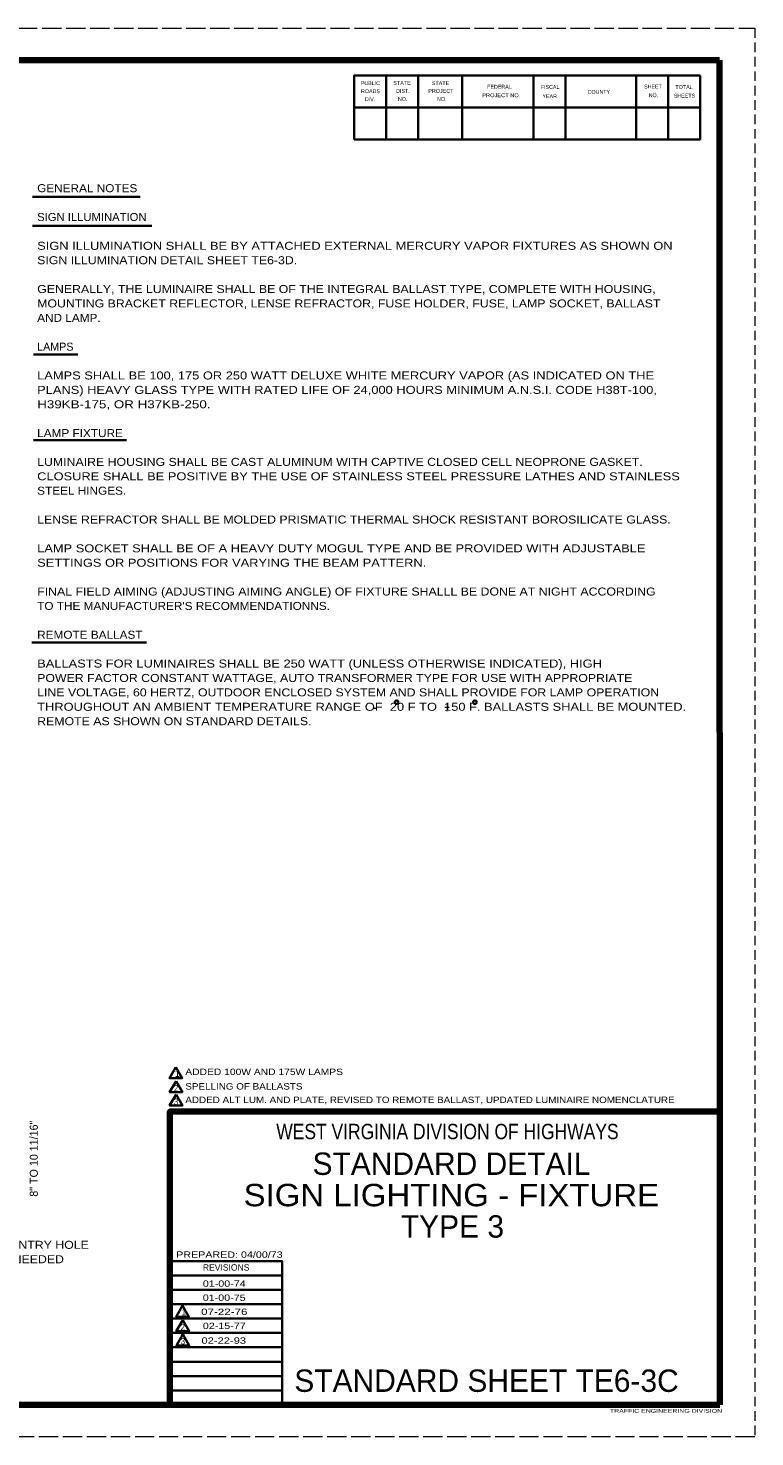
# Model space of a CAD drawing. Extents: x -67 to 613, y -55 to 385.
# Drawn here: x 386.2 to 613.1, y -55.5 to 384.6 of the extents above; entities that cross this region are included whole.
import ezdxf
from ezdxf.enums import TextEntityAlignment as Align

# ---------------------------------------------------------------- set-up
doc = ezdxf.new("R2010")
doc.units = 0
doc.linetypes.add('LONG_DASHED', pattern=[7.5, 6, -1.5])
doc.linetypes.add('MEDIUM_DASHED', pattern=[4.5, 3, -1.5])
doc.layers.add('1', color=7, linetype='Continuous', lineweight=13)
doc.layers.add('61', color=7, linetype='Continuous', lineweight=35)

msp = doc.modelspace()

# ---------------------------------------------------------------- linework, layer by layer
at = {"layer": '1', "linetype": 'MEDIUM_DASHED'}
msp.add_line((613.061, 384.56), (613.041, -55.46), dxfattribs=at)
at = {"layer": '1', "lineweight": 35}
for p, q in [((387.586, 331.879), (421.121, 331.879)), ((387.586, 322.863), (424.831, 322.863)), ((387.868, 282.575), (401.68, 282.575)), ((387.868, 255.811), (416.926, 255.811)), ((387.305, 192.703), (423.13, 192.703)), ((465.441, -5.04), (430.461, -5.04)), ((465.441, -9.54), (430.461, -9.54)), ((465.441, -14.04), (430.461, -14.04)), ((465.441, -18.56), (430.461, -18.56)), ((465.441, -23.04), (430.461, -23.04)), ((465.441, -27.52), (430.461, -27.52)), ((465.441, -32.02), (430.461, -32.02)), ((465.441, -36.52), (430.461, -36.52)), ((465.441, -41.04), (430.461, -41.04))]:
    msp.add_line(p, q, dxfattribs=at)
for points in [[(432.302, 60.038), (430.302, 56.574), (434.302, 56.574)], [(432.358, 55.671), (430.358, 52.207), (434.358, 52.207)], [(432.358, 51.453), (430.358, 47.989), (434.358, 47.989)], [(434.394, -14.481), (432.394, -17.945), (436.394, -17.945)], [(434.432, -19.059), (432.432, -22.523), (436.432, -22.523)], [(434.469, -23.455), (432.469, -26.919), (436.469, -26.919)]]:
    msp.add_lwpolyline(points, close=True, dxfattribs=at)
at = {"layer": '1', "lineweight": 158}
msp.add_lwpolyline([(430.441, -45.48), (430.441, 46.1), (602.101, 46.1)], dxfattribs=at)
at = {"layer": '1', "lineweight": 35}
msp.add_lwpolyline([(465.441, -45.52), (465.441, -0.56), (430.461, -0.56)], dxfattribs=at)
for centre in [(501.246, 174.005), (525.66, 174.005)]:
    msp.add_circle(centre, 0.568, dxfattribs=at)
at = {"layer": '61', "linetype": 'LONG_DASHED', "lineweight": 13}
for p, q in [((-66.959, 384.56), (613.061, 384.56)), ((613.041, -55.46), (-67.019, -55.48))]:
    msp.add_line(p, q, dxfattribs=at)
at = {"layer": '61', "lineweight": 158}
for p, q in [((602.081, 374.56), (602.101, -45.48)), ((602.101, -45.48), (-36.959, -45.46))]:
    msp.add_line(p, q, dxfattribs=at)
at = {"layer": '61'}
for p, q in [((498.001, 369.8), (498.001, 349.8)), ((508.001, 369.8), (508.001, 349.8)), ((521.681, 369.8), (521.681, 349.8)), ((544.001, 369.8), (544.001, 349.8)), ((554.001, 369.8), (554.001, 349.8)), ((575.981, 369.82), (575.981, 349.82)), ((585.981, 369.82), (585.981, 349.82)), ((596.001, 359.78), (487.981, 359.8))]:
    msp.add_line(p, q, dxfattribs=at)
at = {"layer": '61', "lineweight": 158}
msp.add_lwpolyline([(602.081, 374.56), (-36.959, 374.56), (-36.959, -45.46)], dxfattribs=at)
at = {"layer": '61'}
for points in [[(595.981, 369.82), (488.001, 369.8), (488.001, 349.8)], [(595.981, 369.82), (595.981, 349.82), (488.001, 349.8)]]:
    msp.add_lwpolyline(points, dxfattribs=at)

# ---------------------------------------------------------------- texts
at = {"layer": '1'}
for s, height, width, p in [('GENERAL NOTES', 2.5, 1.1, (388.995, 333.323)), ('SIGN ILLUMINATION', 2.5, 1.05, (388.995, 324.323)), ('SIGN ILLUMINATION SHALL BE BY ATTACHED EXTERNAL MERCURY VAPOR FIXTURES AS SHOWN ON', 2.5, 1.2, (388.995, 315.323)), ('SIGN ILLUMINATION DETAIL SHEET TE6-3D.', 2.5, 1.15, (388.995, 310.823)), ('GENERALLY, THE LUMINAIRE SHALL BE OF THE INTEGRAL BALLAST TYPE, COMPLETE WITH HOUSING,', 2.5, 1.15, (388.995, 301.823)), ('MOUNTING BRACKET REFLECTOR, LENSE REFRACTOR, FUSE HOLDER, FUSE, LAMP SOCKET, BALLAST', 2.5, 1.15, (388.995, 297.323)), ('AND LAMP.', 2.5, 1.1, (388.995, 292.823)), ('LAMPS SHALL BE 100, 175 OR 250 WATT DELUXE WHITE MERCURY VAPOR (AS INDICATED ON THE', 2.5, 1.2, (388.995, 274.823)), ('PLANS) HEAVY GLASS TYPE WITH RATED LIFE OF 24,000 HOURS MINIMUM A.N.S.I. CODE H38T-100,', 2.5, 1.2, (388.995, 270.323)), ('H39KB-175, OR H37KB-250.', 2.5, 1.25, (388.995, 265.823)), ('LAMP FIXTURE', 2.5, 1.1, (388.995, 256.823)), ('LUMINAIRE HOUSING SHALL BE CAST ALUMINUM WITH CAPTIVE CLOSED CELL NEOPRONE GASKET.', 2.5, 1.15, (388.995, 247.823)), ('CLOSURE SHALL BE POSITIVE BY THE USE OF STAINLESS STEEL PRESSURE LATHES AND STAINLESS', 2.5, 1.2, (388.995, 243.323)), ('STEEL HINGES.', 2.5, 1.1, (388.995, 238.823)), ('LENSE REFRACTOR SHALL BE MOLDED PRISMATIC THERMAL SHOCK RESISTANT BOROSILICATE GLASS.', 2.5, 1.15, (388.995, 229.823)), ('LAMP SOCKET SHALL BE OF A HEAVY DUTY MOGUL TYPE AND BE PROVIDED WITH ADJUSTABLE', 2.5, 1.2, (388.995, 220.823)), ('SETTINGS OR POSITIONS FOR VARYING THE BEAM PATTERN.', 2.5, 1.2, (388.995, 216.323)), ('FINAL FIELD AIMING (ADJUSTING AIMING ANGLE) OF FIXTURE SHALLL BE DONE AT NIGHT ACCORDING', 2.5, 1.15, (388.995, 207.323)), ("TO THE MANUFACTURER'S RECOMMENDATIONNS.", 2.5, 1.1, (388.995, 202.823)), ('REMOTE BALLAST', 2.5, 1.1, (388.995, 193.823)), ('BALLASTS FOR LUMINAIRES SHALL BE 250 WATT (UNLESS OTHERWISE INDICATED), HIGH', 2.5, 1.2, (388.995, 184.823)), ('POWER FACTOR CONSTANT WATTAGE, AUTO TRANSFORMER TYPE FOR USE WITH APPROPRIATE', 2.5, 1.15, (388.995, 180.323)), ('LINE VOLTAGE, 60 HERTZ, OUTDOOR ENCLOSED SYSTEM AND SHALL PROVIDE FOR LAMP OPERATION', 2.5, 1.15, (388.995, 175.823)), ('THROUGHOUT AN AMBIENT TEMPERATURE RANGE OF  20 F TO  150 F. BALLASTS SHALL BE MOUNTED.', 2.5, 1.2, (388.995, 171.323)), ('+', 4, 0.55, (516.118, 170.513)), ('REMOTE AS SHOWN ON STANDARD DETAILS.', 2.5, 1.15, (388.995, 166.823)), ('ADDED 100W AND 175W LAMPS', 2, 1.2, (435.25, 57.539)), ('2', 2, 0.9, (431.678, 52.434)), ('SPELLING OF BALLASTS', 2, 1.15, (435.25, 53.001)), ('3', 2, 0.9, (431.678, 48.215)), ('ADDED ALT LUM. AND PLATE, REVISED TO REMOTE BALLAST, UPDATED LUMINAIRE NOMENCLATURE', 2, 1.15, (435.25, 48.783)), ('3/4" CONDUIT ENTRY HOLE', 2.5, 1.15, (354.2, 3.247)), ('EACH END AS NEEDED', 2.5, 1.15, (354.2, -1.253)), ('PREPARED: 04/00/73', 1.998, 1.25, (432.401, 0.44)), ('2', 2, 0.9, (433.794, -22.205)), ('3', 2, 0.9, (433.831, -26.601)), ('TRAFFIC ENGINEERING DIVISION', 1.2, 1.35, (567.821, -47.98))]:
    msp.add_text(s, height=height, dxfattribs=dict(at, width=width)).set_placement(p)
for s, height, p in [('LAMPS', 2.5, (388.995, 283.823)), ('-', 4, (493.535, 170.553)), ('1', 2, (432.018, 56.971)), ('REVISIONS', 1.998, (440.721, -3.56)), ('1', 2, (434.06, -17.534)), ('STANDARD SHEET TE6-3C', 6.993, (469.281, -41.44))]:
    msp.add_text(s, height=height, dxfattribs=at).set_placement(p)
msp.add_text('8" TO 10 11/16"', height=2.5, rotation=90, dxfattribs=at).set_placement((389.185, 19.538))
for s, height, width, p in [('WEST VIRGINIA DIVISION OF HIGHWAYS', 4.795, 0.85, (517.089, 37.5)), ('SIGN LIGHTING - FIXTURE', 6.993, 1.1, (518.312, 16.544)), ('01-00-74', 2, 1.25, (447.411, -8.62)), ('01-00-75', 2, 1.25, (447.39, -13.02)), ('07-22-76', 2, 1.35, (447.41, -17.42)), ('02-15-77', 2, 1.25, (447.411, -21.82)), ('02-22-93', 2, 1.3, (447.25, -26.42))]:
    msp.add_text(s, height=height, dxfattribs=dict(at, width=width)).set_placement(p, align=Align.CENTER)
for s, p in [('STANDARD DETAIL', (518.358, 26.34)), ('TYPE 3', (518.649, 6.747))]:
    msp.add_text(s, height=6.993, dxfattribs=at).set_placement(p, align=Align.CENTER)
at = {"layer": '61'}
for s, rotation, p in [('PUBLIC', 0.033, (490.041, 366.78)), ('ROADS', 0.124, (490.121, 364.26)), ('DIST.', 0.056, (501.081, 364.34)), ('FEDERAL', 0.007, (529.501, 365.66)), ('FISCAL', 359.942, (546.241, 365.6)), ('COUNTY', 0.069, (560.861, 364.06)), ('SHEET', 0.059, (578.501, 365.72)), ('DIV.', 359.932, (491.321, 361.76)), ('YEAR', 0.105, (546.761, 362.7)), ('SHEETS', 359.959, (587.781, 362.88))]:
    msp.add_text(s, height=1.201, rotation=rotation, dxfattribs=at).set_placement(p)
for s, rotation, width, p in [('STATE', 0.059, 1.05, (500.201, 366.84)), ('PROJECT', 359.908, 1.05, (511.121, 364.36)), ('STATE', 0.059, 1.05, (512.201, 366.78)), ('TOTAL', 359.926, 1.05, (588.241, 365.58)), ('NO.', 359.852, 0.95, (501.661, 361.82)), ('NO.', 0.225, 0.95, (513.861, 361.82)), ('PROJECT NO.', 359.922, 1.1, (527.961, 363)), ('NO.', 359.852, 0.95, (579.921, 363))]:
    msp.add_text(s, height=1.201, rotation=rotation, dxfattribs=dict(at, width=width)).set_placement(p)

doc.saveas('drawing.dxf')
